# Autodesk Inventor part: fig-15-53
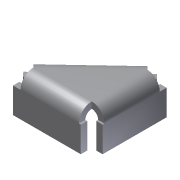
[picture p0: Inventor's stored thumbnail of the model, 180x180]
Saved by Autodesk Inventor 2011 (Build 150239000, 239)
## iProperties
Created: 2008-06
Part Number: fig-15-53
Material: Default
Document SubType Name: Sheet Metal
Designer: CADCIM
Density: 1 g/cm^3
Sheet Metal Rule: Default_mm
Author: CADCIM
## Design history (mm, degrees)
node "Face1"
  sketch "Sketch1"
    geometry: L1 (10.277, 2.151)-(10.277, -5.485); L2 (10.277, -5.485)-(2.197, -5.485); L3 (10.277, 2.151)-(2.197, -5.485)
    constraints: 6 end point
node "Flange2"
body "Solid1"
face "Plate1" dims "Thickness" = 0.5
sketch "Sketch3"
  geometry: L1 (0, -3)-(7.636, -3); L2 (7.636, -3)-(7.636, 0); 2 other entities
  constraints: 4 end point, 4 other
face "Plate3" dims "d16" = 0.5 (= BendReliefWidth), "d17" = 0.25 (= BendReliefDepth), "d18" = 1 (= MinimumRemnant), "d19" = 0.5 (= BendRadius), "d20" = 3, "d21" = 90 deg, "d22" = 0.5 (= BendRadius), "d23" = 2 (= CornerReliefSize), "d24" = 0.5 (= Thickness), "d25" = 0.5 (= JacobiRadiusSize), "SeamGap" = 0.01, "Thickness" = 0.5
bend "Bend2" dims "d16" = 0.5 (= BendReliefWidth), "d17" = 0.25 (= BendReliefDepth), "d18" = 1 (= MinimumRemnant), "d19" = 0.5 (= BendRadius), "d20" = 3, "d21" = 90 deg, "d22" = 0.5 (= BendRadius), "SeamGap" = 0.01, "Thickness" = 0.5
feature "Corner2" dims "d20" = 3, "d21" = 90 deg, "d23" = 2 (= CornerReliefSize), "d24" = 0.5 (= Thickness), "d25" = 0.5 (= JacobiRadiusSize)
other parameters: "BendRadius" = 0.5 (= Thickness), "BendReliefWidth" = 0.5 (= Thickness), "BendReliefDepth" = 0.25 (= 0.5 x Thickness), "CornerReliefSize" = 2 (= 4 x Thickness), "MinimumRemnant" = 1 (= 2 x Thickness), "TransitionRadius" = 0.5 (= BendRadius), "JacobiRadiusSize" = 0.5 (= BendRadius), "d0" = 0.5 (= BendRadius), "GapSize" = 0.5 (= Thickness)
